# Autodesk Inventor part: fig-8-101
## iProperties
Created: 2007-02
Part Number: fig-8-101
Document SubType Name: Modeling
Designer: Administrator
Density: 1 g/cm^3
Author: Administrator
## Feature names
1. Extrusion1
